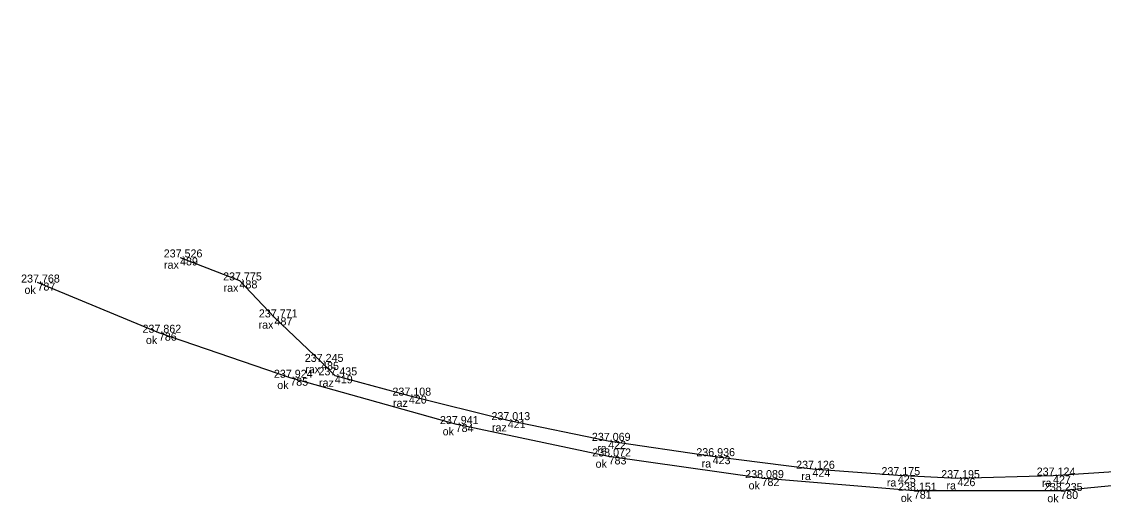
# Model space of a CAD drawing. Extents: x -759609 to -758899, y -1026011 to -1025762.
# Drawn here: x -759609.3 to -759447.1, y -1026010.8 to -1025938.6 of the extents above; entities that cross this region are included whole.
import ezdxf

# ---------------------------------------------------------------- set-up
doc = ezdxf.new("R2010")
doc.units = 0
for name, color, linetype in [('Vrstva 1', 7, 'Continuous'), ('Vrstva 28', 7, 'Continuous'), ('Vrstva 60', 7, 'Continuous'), ('Vrstva 61', 7, 'Continuous'), ('Vrstva 62', 7, 'Continuous')]:
    doc.layers.add(name, color=color, linetype=linetype)

msp = doc.modelspace()

# ---------------------------------------------------------------- linework, layer by layer
at = {"layer": 'Vrstva 1'}
msp.add_lwpolyline([(-759281.05, -1025938.61), (-759297.45, -1025950.26), (-759307.77, -1025956.8), (-759324.07, -1025965.75), (-759343.79, -1025975.91), (-759362.01, -1025985.42), (-759382.21, -1025994.2), (-759406.05, -1026001.87), (-759428.9, -1026006.63), (-759453.52, -1026009.06), (-759475.49, -1026009.02), (-759498.33, -1026007.13), (-759521.27, -1026003.88), (-759544.21, -1025999.02), (-759569.02, -1025992.07), (-759588.73, -1025985.31), (-759606.94, -1025977.78)], dxfattribs=at)
at = {"layer": 'Vrstva 28'}
msp.add_lwpolyline([(-759585.55, -1025974.01), (-759576.63, -1025977.46), (-759571.38, -1025983.01), (-759564.39, -1025989.69), (-759562.33, -1025991.71), (-759551.23, -1025994.75), (-759536.39, -1025998.43), (-759521.33, -1026001.54), (-759505.66, -1026003.84), (-759490.69, -1026005.73), (-759477.88, -1026006.69), (-759468.93, -1026007.14), (-759454.6, -1026006.75), (-759438.66, -1026005.67)], dxfattribs=at)
at = {"layer": 'Vrstva 60'}
for p, q in [((-759585.55, -1025974.01), (-759585.55, -1025974.01)), ((-759576.63, -1025977.46), (-759576.63, -1025977.46)), ((-759606.94, -1025977.78), (-759606.94, -1025977.78)), ((-759571.38, -1025983.01), (-759571.38, -1025983.01)), ((-759588.73, -1025985.31), (-759588.73, -1025985.31)), ((-759564.39, -1025989.69), (-759564.39, -1025989.69)), ((-759569.02, -1025992.07), (-759569.02, -1025992.07)), ((-759562.33, -1025991.71), (-759562.33, -1025991.71)), ((-759551.23, -1025994.75), (-759551.23, -1025994.75)), ((-759536.39, -1025998.43), (-759536.39, -1025998.43)), ((-759544.21, -1025999.02), (-759544.21, -1025999.02)), ((-759521.33, -1026001.54), (-759521.33, -1026001.54)), ((-759521.27, -1026003.88), (-759521.27, -1026003.88)), ((-759505.66, -1026003.84), (-759505.66, -1026003.84)), ((-759490.69, -1026005.73), (-759490.69, -1026005.73)), ((-759477.88, -1026006.69), (-759477.88, -1026006.69)), ((-759454.6, -1026006.75), (-759454.6, -1026006.75)), ((-759498.33, -1026007.13), (-759498.33, -1026007.13)), ((-759468.93, -1026007.14), (-759468.93, -1026007.14)), ((-759475.49, -1026009.02), (-759475.49, -1026009.02)), ((-759453.52, -1026009.06), (-759453.52, -1026009.06))]:
    msp.add_line(p, q, dxfattribs=at)

# ---------------------------------------------------------------- texts
for s, p in [('489', (-759585.55, -1025975.21)), ('787', (-759606.94, -1025978.98)), ('488', (-759576.63, -1025978.66)), ('487', (-759571.38, -1025984.21)), ('786', (-759588.73, -1025986.51)), ('485', (-759564.39, -1025990.89)), ('785', (-759569.02, -1025993.27)), ('419', (-759562.33, -1025992.91)), ('420', (-759551.23, -1025995.95)), ('421', (-759536.39, -1025999.63)), ('784', (-759544.21, -1026000.22)), ('422', (-759521.33, -1026002.74)), ('783', (-759521.27, -1026005.08)), ('423', (-759505.66, -1026005.04)), ('424', (-759490.69, -1026006.93)), ('425', (-759477.88, -1026007.89)), ('427', (-759454.6, -1026007.95)), ('782', (-759498.33, -1026008.33)), ('426', (-759468.93, -1026008.34)), ('781', (-759475.49, -1026010.22)), ('780', (-759453.52, -1026010.26))]:
    msp.add_text(s, height=1.2, dxfattribs=at).set_placement(p)
at = {"layer": 'Vrstva 61'}
for s, p in [('237.526', (-759588, -1025974.01)), ('237.768', (-759609.39, -1025977.78)), ('237.775', (-759579.09, -1025977.46)), ('237.771', (-759573.73, -1025983.01)), ('237.862', (-759591.18, -1025985.31)), ('237.245', (-759566.84, -1025989.69)), ('237.435', (-759564.79, -1025991.71)), ('237.924', (-759571.47, -1025992.07)), ('237.108', (-759553.69, -1025994.75)), ('237.013', (-759538.84, -1025998.43)), ('237.941', (-759546.57, -1025999.02)), ('237.069', (-759523.78, -1026001.54)), ('238.072', (-759523.72, -1026003.88)), ('236.936', (-759508.11, -1026003.84)), ('237.126', (-759493.14, -1026005.73)), ('238.089', (-759500.78, -1026007.13)), ('237.175', (-759480.34, -1026006.69)), ('237.195', (-759471.38, -1026007.14)), ('237.124', (-759457.05, -1026006.75)), ('238.151', (-759477.85, -1026009.02)), ('238.235', (-759455.97, -1026009.06))]:
    msp.add_text(s, height=1.2, dxfattribs=at).set_placement(p)
at = {"layer": 'Vrstva 62'}
for s, p in [('rax', (-759587.95, -1025975.71)), ('ok', (-759608.89, -1025979.48)), ('rax', (-759579.03, -1025979.16)), ('rax', (-759573.78, -1025984.71)), ('ok', (-759590.67, -1025987.01)), ('rax', (-759566.78, -1025991.39)), ('ok', (-759570.97, -1025993.77)), ('raz', (-759564.71, -1025993.41)), ('raz', (-759553.61, -1025996.45)), ('ok', (-759546.16, -1026000.72)), ('raz', (-759538.77, -1026000.13)), ('ra', (-759522.99, -1026003.24)), ('ok', (-759523.22, -1026005.58)), ('ra', (-759507.32, -1026005.54)), ('ra', (-759492.35, -1026007.43)), ('ok', (-759500.27, -1026008.83)), ('ra', (-759479.54, -1026008.39)), ('ra', (-759470.59, -1026008.84)), ('ra', (-759456.26, -1026008.45)), ('ok', (-759477.44, -1026010.72)), ('ok', (-759455.46, -1026010.76))]:
    msp.add_text(s, height=1.2, dxfattribs=at).set_placement(p)

doc.saveas('drawing.dxf')
